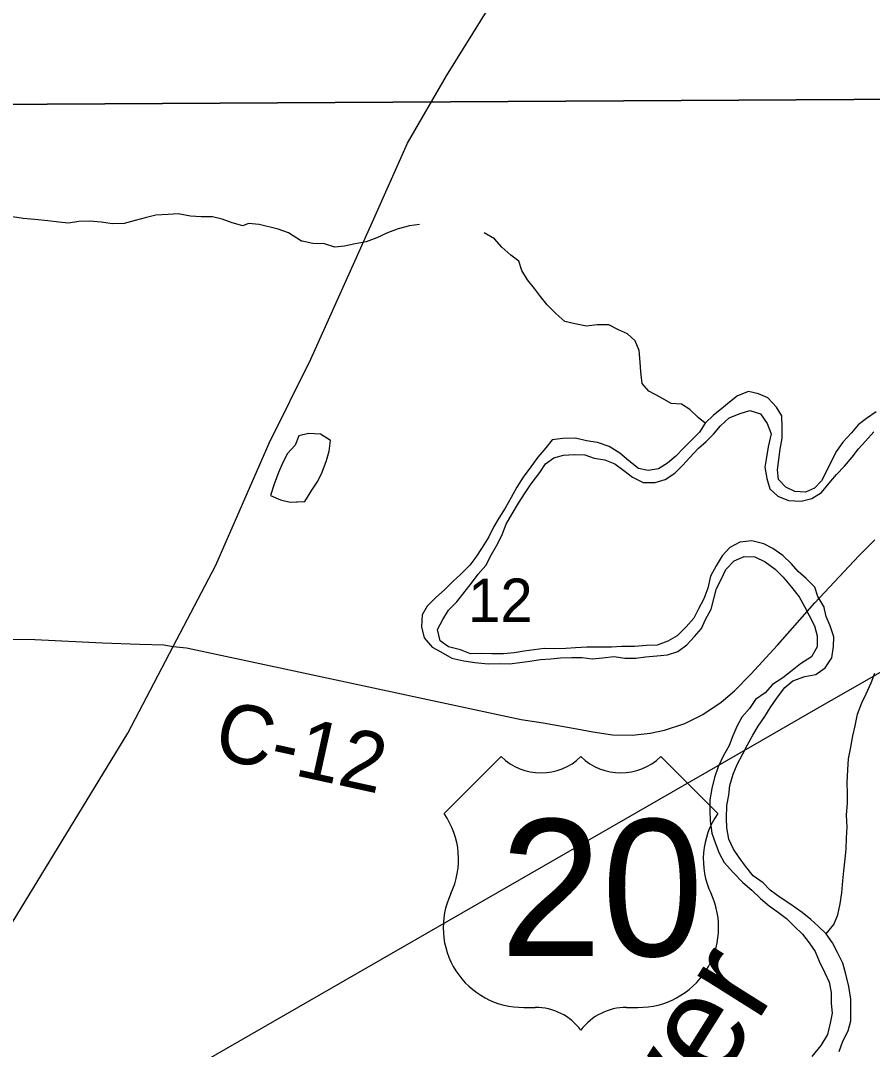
# Model space of a CAD drawing. Extents: x 1857828 to 2277390, y 930619 to 1324581.
# Drawn here: x 2065754 to 2070089, y 1205159 to 1210395 of the extents above; entities that cross this region are included whole.
import ezdxf

# ---------------------------------------------------------------- set-up
doc = ezdxf.new("R2010")
doc.units = 0
for name, color, linetype in [('GM_X_County_Road', 7, 'Continuous'), ('GM_X_County_Road_Text', 7, 'Continuous'), ('GM_X_Major_River', 7, 'Continuous'), ('GM_X_Major_River_Text', 7, 'Continuous'), ('GM_X_Minor_Lake', 7, 'Continuous'), ('GM_X_Minor_River', 7, 'Continuous'), ('GM_X_Section', 7, 'Continuous'), ('GM_X_Section_Text', 7, 'Continuous'), ('GM_X_Township_Road', 7, 'Continuous'), ('GM_X_US_Location', 7, 'Continuous'), ('GM_X_US_Route', 7, 'Continuous'), ('GM_X_US_Shield', 7, 'Continuous')]:
    doc.layers.add(name, color=color, linetype=linetype)

msp = doc.modelspace()

# ---------------------------------------------------------------- linework, layer by layer
at = {"layer": 'GM_X_County_Road'}
for points in [[(2066531.4, 1207209.6), (2066748.3, 1207622.9), (2067019.5, 1208243.8), (2067230.4, 1208672.8), (2067544.5, 1209371.4), (2067723.1, 1209770.7), (2067921.2, 1210113.6), (2068314.7, 1210749.2), (2068791, 1211438), (2069236.8, 1212075.7), (2069293.3, 1212158.3), (2069322.4, 1212203), (2069486.1, 1212444), (2069556.3, 1212547), (2069679.3, 1212692.7), (2069759.2, 1212787.5), (2069976.1, 1213011.8), (2070298.7, 1213385.4), (2070312.8, 1213403.7), (2070367.8, 1213475), (2070506.1, 1213672), (2070673.6, 1213969.1), (2070796.3, 1214162.7)], [(2066531.4, 1207209.6), (2066599.1, 1207203.5), (2066749.3, 1207170.6), (2067145.6, 1207085.7), (2068300.7, 1206838.7), (2068412.8, 1206821.6), (2068584.8, 1206791), (2068666.9, 1206775.6), (2068767, 1206760.4), (2068866.9, 1206759.2), (2068958.7, 1206768), (2069030.5, 1206784.6), (2069134.1, 1206817.5), (2069225.7, 1206864.4), (2069319.1, 1206927.2), (2069386.5, 1206983.9), (2069469.7, 1207068.7), (2069606.3, 1207216.2), (2069796.4, 1207432.1), (2070020.1, 1207670.4), (2070101.3, 1207753.3)], [(2060140.1, 1201171.9), (2060205.6, 1201229.4), (2061510.6, 1202210.1), (2062685.1, 1203178.1), (2063045, 1203479.1), (2063443.3, 1203807.8), (2063817.2, 1204104.5), (2064372.5, 1204503.7), (2065003.2, 1205016.3), (2065250.1, 1205245.6), (2065353, 1205315.3), (2065456.4, 1205422.5), (2065629.4, 1205673.4), (2066300.4, 1206769.3), (2066531.4, 1207209.6)]]:
    msp.add_lwpolyline(points, dxfattribs=at)
at = {"layer": 'GM_X_Major_River'}
for points in [[(2070107.4, 1208404.3), (2070059.5, 1208370.2), (2070015.6, 1208338.1), (2069981.7, 1208297.9), (2069937.8, 1208249.8), (2069905.9, 1208203.6), (2069878, 1208147.5), (2069854.1, 1208099.3), (2069830.2, 1208053.2), (2069794.3, 1208015.1), (2069748.3, 1207994.9), (2069694.3, 1207998.9), (2069648.3, 1208020.9), (2069610.2, 1208058.9), (2069606.1, 1208109), (2069611.9, 1208161.1), (2069619.8, 1208213.2), (2069629.7, 1208269.4), (2069629.6, 1208323.5), (2069627.4, 1208383.6), (2069601.3, 1208427.7), (2069557.2, 1208475.7), (2069509.2, 1208495.7), (2069459.1, 1208507.7), (2069403.2, 1208485.6), (2069361.2, 1208453.4), (2069321.3, 1208419.3), (2069279.4, 1208387.2), (2069237.5, 1208347), (2069209.6, 1208300.9), (2069163.7, 1208254.7), (2069127.7, 1208218.6), (2069087.8, 1208178.4), (2069045.9, 1208142.3), (2069000, 1208114.2), (2068948, 1208106.1), (2068897.9, 1208116), (2068849.8, 1208154.1), (2068803.7, 1208194.1), (2068749.7, 1208228.1), (2068689.6, 1208248), (2068633.6, 1208256), (2068577.5, 1208269.9), (2068513.5, 1208267.8), (2068459.5, 1208261.7), (2068427.6, 1208221.6), (2068385.7, 1208173.4), (2068349.9, 1208123.3), (2068312, 1208071.1), (2068280.1, 1208021), (2068250.2, 1207968.8), (2068220.3, 1207914.6), (2068188.4, 1207862.5), (2068160.5, 1207816.3), (2068136.6, 1207768.2), (2068102.8, 1207714), (2068070.9, 1207663.9), (2068041, 1207623.8), (2067993.1, 1207575.6), (2067955.1, 1207541.5), (2067913.2, 1207499.3), (2067865.3, 1207457.1), (2067823.4, 1207415), (2067797.5, 1207370.9), (2067793.7, 1207310.7), (2067807.8, 1207254.6), (2067847.9, 1207206.6), (2067892, 1207182.6), (2067948, 1207150.6), (2068010.1, 1207136.6), (2068066.1, 1207128.7), (2068134.1, 1207120.8), (2068192.1, 1207122.8), (2068242.2, 1207120.9), (2068294.1, 1207129)], [(2068578, 1207203.6), (2068528, 1207199.5), (2068472, 1207197.4), (2068418, 1207199.3), (2068368, 1207193.3), (2068316, 1207185.2), (2068266, 1207177.1), (2068212, 1207173), (2068152, 1207172.9), (2068100, 1207174.8), (2068044, 1207172.8), (2067992, 1207192.7), (2067931.9, 1207208.7), (2067889.8, 1207238.7), (2067875.7, 1207296.8), (2067903.6, 1207346.9), (2067931.5, 1207395.1), (2067973.4, 1207437.2), (2068017.3, 1207491.4), (2068049.2, 1207531.6), (2068083.1, 1207577.7), (2068121, 1207621.9), (2068150.9, 1207678), (2068176.8, 1207722.2), (2068202.6, 1207774.3), (2068224.5, 1207832.5), (2068256.4, 1207884.6), (2068288.3, 1207938.8), (2068322.2, 1207991), (2068352.1, 1208037.1), (2068395.9, 1208095.3), (2068425.8, 1208139.4), (2068467.8, 1208169.6), (2068517.7, 1208183.6), (2068571.7, 1208187.7), (2068625.7, 1208185.8), (2068673.8, 1208167.8), (2068727.8, 1208159.9), (2068777.9, 1208139.9), (2068824, 1208105.9), (2068868, 1208071.9), (2068922.1, 1208043.9), (2068984.1, 1208044), (2069034.1, 1208060.1), (2069084, 1208092.2), (2069123.9, 1208132.4), (2069157.9, 1208170.5), (2069203.7, 1208218.7), (2069243.7, 1208252.8), (2069279.6, 1208290.9), (2069315.5, 1208333.1), (2069359.4, 1208373.2), (2069415.4, 1208395.4), (2069465.3, 1208411.5), (2069519.4, 1208393.5), (2069553.5, 1208345.4), (2069573.6, 1208291.4), (2069557.8, 1208225.2), (2069549.9, 1208173.1), (2069542, 1208122.9), (2069552.2, 1208064.8), (2069566.3, 1208012.7), (2069608.4, 1207974.7), (2069662.4, 1207952.7), (2069726.4, 1207948.8), (2069780.4, 1207962.9), (2069830.4, 1207993.1), (2069868.2, 1208041.2), (2069906.2, 1208085.4), (2069946.1, 1208127.5), (2069986, 1208173.7), (2070017.9, 1208215.8), (2070053.8, 1208253.9), (2070095.7, 1208302.1)], [(2069811.6, 1207463.9), (2069795.5, 1207511.9), (2069751.4, 1207556), (2069711.3, 1207592), (2069677.2, 1207630), (2069633.1, 1207672.1), (2069583, 1207708.1), (2069536.9, 1207732.1), (2069474.9, 1207748), (2069414.9, 1207739.9), (2069362.9, 1207713.8), (2069325, 1207671.6), (2069293.1, 1207619.5), (2069265.3, 1207567.3), (2069251.4, 1207507.2), (2069231.5, 1207453), (2069203.6, 1207400.9), (2069179.7, 1207354.7), (2069141.8, 1207310.6), (2069095.9, 1207264.4), (2069048, 1207236.3), (2068994, 1207216.2), (2068940, 1207214.1), (2068878, 1207210), (2068814, 1207209.9), (2068762, 1207205.8), (2068696, 1207205.8), (2068636, 1207205.6), (2068578, 1207203.6)], [(2068294.1, 1207129), (2068346.1, 1207135.1), (2068400.1, 1207143.2), (2068452.1, 1207147.3), (2068502.1, 1207151.3), (2068560.1, 1207153.4), (2068612.1, 1207153.5), (2068662.1, 1207147.6), (2068716.1, 1207151.6), (2068774.1, 1207159.7), (2068828.2, 1207149.8), (2068884.2, 1207149.9), (2068934.2, 1207158), (2068992.2, 1207162.1), (2069046.2, 1207168.1), (2069098.1, 1207184.2), (2069144, 1207218.4), (2069184, 1207260.5), (2069219.9, 1207300.7), (2069239.8, 1207346.8), (2069267.7, 1207399), (2069281.5, 1207453.1), (2069295.4, 1207505.2), (2069319.3, 1207551.4), (2069343.2, 1207601.5), (2069385.1, 1207645.7), (2069437, 1207667.8), (2069491.1, 1207665.9), (2069543.1, 1207639.9), (2069593.2, 1207603.9), (2069635.3, 1207561.8), (2069677.4, 1207511.8), (2069715.6, 1207461.7), (2069743.7, 1207413.7), (2069767.8, 1207367.6), (2069793.9, 1207315.5), (2069808, 1207263.4), (2069808.2, 1207207.3), (2069778.3, 1207157.1), (2069722.4, 1207121), (2069680.4, 1207086.8), (2069632.5, 1207050.7), (2069580.6, 1207016.6), (2069542.7, 1206974.4), (2069494.7, 1206940.3), (2069462.8, 1206894.1), (2069424.9, 1206850), (2069399, 1206801.8), (2069379.1, 1206755.7), (2069359.3, 1206705.6), (2069329.4, 1206651.4), (2069303.5, 1206597.2), (2069285.6, 1206543.1), (2069271.8, 1206486.9), (2069261.9, 1206428.8), (2069262, 1206376.7), (2069264.1, 1206322.6), (2069272.3, 1206260.5), (2069290.4, 1206206.4), (2069308.5, 1206158.3), (2069334.6, 1206110.2), (2069382.8, 1206058.1), (2069428.9, 1206008.1), (2069475, 1205970.1), (2069519.1, 1205928.1), (2069563.2, 1205890), (2069611.3, 1205856), (2069651.3, 1205826), (2069691.4, 1205786), (2069733.5, 1205745.9), (2069767.6, 1205701.9), (2069797.7, 1205657.8), (2069817.9, 1205607.8), (2069846, 1205549.7), (2069868.1, 1205501.6), (2069878.2, 1205449.5), (2069878.4, 1205393.4), (2069884.5, 1205343.3), (2069874.6, 1205293.1), (2069860.7, 1205235), (2069826.8, 1205178.8), (2069781, 1205122.6)], [(2069918.9, 1205148.9), (2069938.8, 1205201), (2069964.7, 1205253.2), (2069978.6, 1205305.3), (2069978.5, 1205357.4), (2069978.3, 1205415.6), (2069968.2, 1205479.7), (2069954, 1205541.8), (2069937.9, 1205597.9), (2069911.8, 1205652), (2069885.7, 1205702.1), (2069853.5, 1205748.1), (2069813.4, 1205786.1), (2069775.4, 1205820.2), (2069731.3, 1205856.2), (2069673.2, 1205896.2), (2069619.1, 1205932.2), (2069569, 1205970.2), (2069532.9, 1206006.2), (2069482.8, 1206042.3), (2069442.7, 1206092.3), (2069410.6, 1206136.4), (2069382.5, 1206178.4), (2069358.4, 1206228.5), (2069348.2, 1206286.6), (2069346.1, 1206336.7), (2069348, 1206400.9), (2069357.8, 1206453), (2069363.7, 1206503.1), (2069379.6, 1206559.3), (2069401.5, 1206609.4), (2069429.4, 1206663.6), (2069453.3, 1206709.7), (2069481.2, 1206757.8), (2069507.1, 1206804), (2069540.9, 1206854.1), (2069568.8, 1206898.3), (2069606.7, 1206952.4), (2069642.6, 1207000.6), (2069684.5, 1207034.7), (2069744.5, 1207056.9), (2069800.5, 1207067), (2069848.4, 1207101.1), (2069882.3, 1207151.3), (2069890.2, 1207209.4), (2069892.1, 1207259.5), (2069873.9, 1207315.6), (2069853.8, 1207361.7), (2069841.7, 1207415.8), (2069841.7, 1207413.8), (2069811.6, 1207463.9)]]:
    msp.add_lwpolyline(points, dxfattribs=at)
at = {"layer": 'GM_X_Minor_Lake'}
for points in [[(2067169.5, 1208282.6), (2067151.3, 1208234.6), (2067113.1, 1208192.6), (2067088.9, 1208146.6), (2067066.7, 1208094.6), (2067044.5, 1208036.6), (2067026.2, 1207978.6), (2067076.1, 1207956.3), (2067126.1, 1207944), (2067200.6, 1207948.5)], [(2067169.5, 1208282.6), (2067151.3, 1208234.6), (2067113.1, 1208192.6), (2067088.9, 1208146.6), (2067066.7, 1208094.6), (2067044.5, 1208036.6), (2067026.2, 1207978.6), (2067076.1, 1207956.3), (2067126.1, 1207944), (2067188.1, 1207947.7)], [(2067200.6, 1207948.5), (2067236.3, 1208005.6), (2067266.5, 1208051.6), (2067288.7, 1208097.6), (2067311, 1208155.6), (2067325.2, 1208203.7), (2067331.4, 1208257.8), (2067279.5, 1208290.1), (2067219.6, 1208294.4), (2067169.5, 1208282.6)], [(2067200.1, 1207947.7), (2067236.3, 1208005.6), (2067266.5, 1208051.6), (2067288.7, 1208097.6), (2067311, 1208155.6), (2067325.2, 1208203.7), (2067331.4, 1208257.8), (2067279.5, 1208290.1), (2067219.6, 1208294.4), (2067169.5, 1208282.6)]]:
    msp.add_lwpolyline(points, dxfattribs=at)
at = {"layer": 'GM_X_Minor_River'}
for points in [[(2066884.8, 1209350), (2066830.8, 1209366), (2066780.7, 1209383.9), (2066730.7, 1209395.9), (2066672.7, 1209395.8), (2066618.7, 1209399.7), (2066556.6, 1209411.7), (2066504.6, 1209407.6), (2066442.6, 1209405.5), (2066388.7, 1209391.4), (2066336.7, 1209377.3), (2066280.7, 1209363.2), (2066222.7, 1209361.1), (2066164.7, 1209369), (2066104.7, 1209375), (2066050.7, 1209372.9), (2065998.7, 1209364.8), (2065948.7, 1209368.7), (2065892.6, 1209376.7), (2065826.6, 1209382.6), (2065766.6, 1209388.5), (2065712.6, 1209396.5)], [(2067784.9, 1209357.2), (2067784.9, 1209357.2), (2067732.9, 1209351.2), (2067675, 1209335.1), (2067621, 1209314.9), (2067567.1, 1209288.8), (2067513.1, 1209268.7), (2067457.1, 1209258.6), (2067403.1, 1209246.5), (2067353.1, 1209242.4), (2067301.1, 1209258.4), (2067241.1, 1209260.3), (2067187, 1209272.2), (2067183, 1209272.2), (2067116.9, 1209314.2), (2067064.9, 1209334.2), (2066968.8, 1209358.1), (2066914.8, 1209362.1), (2066884.8, 1209350), (2066884.8, 1209350)], [(2069237.5, 1208347), (2069201.4, 1208375), (2069159.3, 1208415.1), (2069117.2, 1208443.1), (2069065.2, 1208447), (2069009.1, 1208479), (2068951, 1208509), (2068916.9, 1208549), (2068910.8, 1208607.1), (2068906.7, 1208657.2), (2068902.6, 1208715.4), (2068882.4, 1208765.4), (2068842.4, 1208801.5), (2068796.3, 1208821.5), (2068748.2, 1208847.4), (2068688.2, 1208847.4), (2068634.2, 1208839.3), (2068574.2, 1208851.2), (2068524.2, 1208863.2), (2068478.1, 1208905.2), (2068434, 1208949.2), (2068399.9, 1208991.3), (2068369.8, 1209031.3), (2068333.7, 1209075.4), (2068305.5, 1209123.4), (2068289.4, 1209171.5), (2068249.4, 1209201.6), (2068203.3, 1209241.6), (2068165.1, 1209283.6), (2068113.1, 1209315.6)], [(2069853.5, 1205748.1), (2069893.4, 1205794.3), (2069913.3, 1205844.4), (2069925.2, 1205900.6), (2069933.1, 1205956.7), (2069938.9, 1206016.8), (2069942.8, 1206068.9), (2069950.7, 1206129.1), (2069954.6, 1206179.2), (2069956.4, 1206235.3), (2069960.3, 1206289.5), (2069956.2, 1206351.6), (2069962, 1206413.8), (2069961.9, 1206463.9), (2069959.8, 1206518), (2069963.6, 1206582.1), (2069967.5, 1206638.2), (2069977.4, 1206688.4), (2069989.2, 1206754.5), (2070001.1, 1206806.7), (2070013, 1206864.8), (2070034.9, 1206923), (2070056.7, 1206969.1), (2070082.6, 1207025.3), (2070100.5, 1207073.4)]]:
    msp.add_lwpolyline(points, dxfattribs=at)
at = {"layer": 'GM_X_Section'}
for points in [[(2065650.4, 1215720.9), (2070962.6, 1215728.7), (2070874.1, 1209998.9), (2065593.7, 1209968.9)], [(2065593.7, 1209968.9), (2070874.1, 1209998.9), (2070799.7, 1204378.1), (2065519.4, 1204352.4)]]:
    msp.add_lwpolyline(points, close=True, dxfattribs=at)
at = {"layer": 'GM_X_Township_Road'}
msp.add_lwpolyline([(2064549.9, 1207247.2), (2065826.7, 1207244.8), (2066171.3, 1207228), (2066359.2, 1207221.5), (2066483.1, 1207218.6), (2066531.4, 1207209.6)], dxfattribs=at)
at = {"layer": 'GM_X_US_Route'}
for points in [[(2069304.1, 1206604.3), (2069801.1, 1206890.3), (2071610, 1207926.4)], [(2054677.9, 1195170.3), (2054837.4, 1195352.9), (2055032, 1195549.7), (2055173.6, 1195679.7), (2055317.8, 1195799.7), (2056203.6, 1196482.3), (2056601.3, 1196831.2), (2057041, 1197329.5), (2057849.7, 1198281.9), (2058613.4, 1199064.3), (2059059.7, 1199476.8), (2059264.5, 1199666), (2059500.2, 1199857.9), (2059938.7, 1200214.7), (2060131.4, 1200354.4), (2065339.2, 1204278.5), (2065730.3, 1204538.2), (2066214.7, 1204827.1), (2069304.1, 1206604.3)]]:
    msp.add_lwpolyline(points, dxfattribs=at)
at = {"layer": 'GM_X_US_Shield'}
for p, q in [((2068199.4, 1206649.4), (2067909.4, 1206359.4)), ((2069301.6, 1206359.4), (2069011.6, 1206649.4)), ((2068315.5, 1205373.3), (2068373.5, 1205373.3)), ((2068837.5, 1205373.3), (2068895.5, 1205373.3))]:
    msp.add_line(p, q, dxfattribs=at)
for centre, radius, start, end in [((2068402.5, 1206856.6), 290, 225.573, 314.427), ((2068808.5, 1206856.6), 290, 225.573, 314.427), ((2067576.8, 1206126.5), 406.1, 334.5471, 35.0009), ((2069634.2, 1206126.5), 406.1, 144.9991, 205.4529), ((2068310.9, 1205779.3), 406.1, 154.8319, 270.6383), ((2068900.1, 1205779.3), 406.1, 269.3617, 25.1681), ((2068373.5, 1205083.2), 290, 36.8699, 90), ((2068837.5, 1205083.2), 290, 90, 143.1301)]:
    msp.add_arc(centre, radius, start, end, dxfattribs=at)

# ---------------------------------------------------------------- texts
at = {"layer": 'GM_X_County_Road_Text'}
msp.add_text('C-12', height=300, rotation=347.6166, dxfattribs=at).set_placement((2066727.3, 1206646.7))
at = {"layer": 'GM_X_Major_River_Text'}
msp.add_text('River', height=500.24, rotation=57.8194, dxfattribs=at).set_placement((2068787.1, 1204159.1))
at = {"layer": 'GM_X_Section_Text'}
msp.add_text('12', height=221, rotation=0, dxfattribs=at).set_placement((2068031.3, 1207334.5))
at = {"layer": 'GM_X_US_Location'}
for s in ['0', '/']:
    msp.add_text(s, height=1, dxfattribs=at).set_placement((2068605.2, 1205976.9))
msp.add_text('20', height=1, rotation=0, dxfattribs=at).set_placement((2068398.7, 1205769.9))
at = {"layer": 'GM_X_US_Shield'}
msp.add_text('20', height=696.1, dxfattribs=at).set_placement((2068193.9, 1205634.3))

doc.saveas('drawing.dxf')
